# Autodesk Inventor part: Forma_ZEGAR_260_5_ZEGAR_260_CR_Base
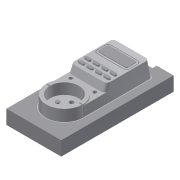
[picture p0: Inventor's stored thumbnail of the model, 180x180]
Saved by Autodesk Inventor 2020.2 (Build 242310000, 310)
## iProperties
Created: 2015-01
Part Number: Forma_ZEGAR_260_5_ZEGAR_260_CR_Base
Material: Ogólny
Document SubType Name: Modeling
Designer: F.Stasiak
Density: 1 g/cm^3
Appearance: Domyślna
Catalog Web Link: www.expertbooks.pl
Manager: www.cadconsulting.pl
Company: Fabian Stasiak CAD Consulting
Author: F.Stasiak
Subject: Zbiór ćwiczeń. Autodesk Inventor 2020. Kurs Professional
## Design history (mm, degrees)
node "Forma_ZEGAR_260_4_ZEGAR_260_MP"
feature "Rzeźbienie1"
feature "Bryła3::Forma_ZEGAR_260_4_ZEGAR_260_MP"
tag "Bryła wyprowadzona1"
node "Bryła1"
feature "Forma_ZEGAR_260_4_ZEGAR_260_MP_Bodies"
feature "Powierzchnia1"
body "Srf1"
